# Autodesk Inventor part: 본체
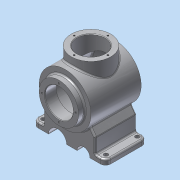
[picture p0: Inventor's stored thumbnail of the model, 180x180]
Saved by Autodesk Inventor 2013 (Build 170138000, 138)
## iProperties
Created: 2018-08
Part Number: 본체
Material: 알루미늄 6061
Document SubType Name: Modeling
Designer: Administrator
Density: 2.71 g/cm^3
Mass: 1888.21 g
Surface Area: 1092.87 cm^2
Volume: 696.756 cm^3
Author: Administrator
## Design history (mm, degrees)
sketch "스케치2"
  geometry: L1 (-70, 40)-(70, 40); L2 (70, 40)-(70, -40); L3 (70, -40)-(-70, -40); L4 (-70, -40)-(-70, 40); L5 (-70, 40)-(70, -40); L6 (70, 40)-(-70, -40); 1 further point
  constraints: 12 end point, 2 midpoint, 2 parallel, 1 horizontal, 1 perpendicular
  dimensions: "d0" = 140 distance of L2.end L3.end; "d1" = 80 distance of L1.end L2.end
extrude "돌출1" new body sketch "스케치2" distance "d2" = 10; taper "d3" = 0 deg
fillet "모깎기1" dims "d4" = 10
sketch "스케치3"
  geometry: L1 (0, 30)-(0, -30) reference; L2 (82, 60)-(82, -60); L3 (120, 60)-(120, 48); L4 (120, 48)-(132, 48); L5 (132, 48)-(132, -48.671); L6 (120, 60)-(82, 60); A1 r 116 centre (82, 56) between (82, -60) and (132, -48.671); 1 further point
  constraints: 10 end point, 2 parallel, 2 perpendicular, 2 point on circle, 1 centre point, 1 horizontal alignment, 1 point on line
  dimensions: "d6" = 120 distance of L2.start L2.end; "d7" = 60 vertical distance of point (0, 0) L2.start; "d8" = 82 distance between parallel lines of L1 L2; "d9" = 76 diameter of L3 L2; "d10" = 100 diameter of L5 L2; "d11" = 12 distance of L3.start L3.end; "d12" = 116 radius of A1
revolve "회전1" sketch "스케치3" stored, may be unused: angle "d13" = 90 deg
sketch "스케치4"
  geometry: L1 (44, 60)-(120, 60) reference; L2 (109, 60)-(109, 38); L3 (109, 38)-(122, 38); L4 (122, 38)-(122, -42.163); L5 (82, 60)-(82, -60); L6 (109, 60)-(82, 60); A1 r 116 centre (82, 56) between (32, -48.671) and (132, -48.671) reference; A2 r 106 centre (82, 56) between (82, -50) and (122, -42.163); 1 further point
  constraints: 10 end point, 3 perpendicular, 3 point on circle, 2 point on line, 1 centre point, 1 midpoint, 1 parallel
  dimensions: "d14" = 54 diameter of L2 L5; "d16" = 22 distance of L2.start L2.end; "d17" = 80 diameter of L4 L5; "d18" = 10 radial gap between concentric circles of A1 A2
revolve "회전2" sketch "스케치4" stored, may be unused: angle "d19" = 90 deg
node "작업 평면1"
chamfer "모따기1" distance "d41" = 1; stored, may be unused: second distance "d42" = 2, angle "d43" = 45 deg
sketch "스케치9"
  geometry: C1 r 38 at (0, 0) reference; 2 further points
  constraints: 1 vertical alignment
  dimensions: "d44" = 32.5 distance of C1.centre point (0, 32.5)
hole "구멍1" sketch "스케치9" at (0, 32.5) diameter "d45" = 3.242; stored, may be unused: countersink angle "d49" = 90 deg, drill point angle "d51" = 118 deg; dims "d46" = 8, "d47" = 4, "d48" = 2, "d50" = 10
fillet "모깎기3" dims "d66" = 3
fillet "모깎기4" dims "d67" = 3
node "작업 평면2"
sketch "스케치13"
  geometry: L1 (60, 0)-(-60, 0) reference; C1 r 32.5 at (0, 82); 1 further point
  constraints: 1 centre point, 1 other
  dimensions: "d73" = 65 diameter of C1; "d74" = 82 distance from line of L1 C1.centre; "d75" = 101.60709 distance of L1.start C1.centre
feature "엠보싱1" sketch "스케치13" dims "d0" = 140, "d1" = 80, "d6" = 120, "d7" = 60, "d8" = 82, "d9" = 76, "d10" = 100, "d11" = 12, "d12" = 116, "d76" = 0.5, "d77" = 0
sketch "스케치15"
  geometry: L1 (0, 10)-(120, 10) reference; L2 (-10, 10)-(-10, 0) reference; L3 (130, 0)-(130, 10) reference; L4 (19.696, 52.41)-(10, 38.563); L5 (110, 38.563)-(100.304, 52.41); L6 (10, 38.563)-(10, 10); L7 (120, 10)-(0, 10) reference; L8 (110, 38.563)-(110, 10); L9 (10, 10)-(110, 10); A1 r 50 centre (60, 82) between (100.304, 52.41) and (19.696, 52.41) reference; A2 r 50 centre (60, 82) between (19.696, 52.41) and (100.304, 52.41); 1 further point
  constraints: 10 end point, 4 point on circle, 2 perpendicular, 2 point on line, 1 centre point, 1 collinear, 1 parallel
  dimensions: "d82" = 35 deg angle of L4 L2; "d83" = 20 distance from line of L6.end L2; "d84" = 20 distance between parallel lines of L3 L8; "d85" = 35 deg angle of L3 L5; "d86" = 0 distance from line of L3.end L5
extrude "돌출4" join sketch "스케치15" distance "d87" = 80; taper "d88" = 0 deg
sketch "스케치16"
  geometry: L1 (120, 0)-(0, 0) reference; C1 r 17.5 at (37.5, 0); 1 further point
  constraints: 1 centre point, 1 point on line
  dimensions: "d89" = 17.5 radius of C1; "d90" = 22.5 distance of C1.centre point (60, 0)
extrude "돌출5" cut sketch "스케치16" stored distance "d91" = 80; taper "d92" = 0 deg
sketch "스케치17"
  geometry: L1 (0, 0)-(-65, 0) reference; C1 r 12.5 at (-32.5, 0); 1 further point
  constraints: 1 centre point, 1 midpoint
  dimensions: "d93" = 12.5 radius of C1; "d94" = 27.5 distance of C1.centre point (-60, 0)
extrude "돌출6" cut sketch "스케치17" stored distance "d95" = 80; taper "d96" = 0 deg
fillet "모깎기5" dims "d97" = 3
fillet "모깎기6" dims "d98" = 3
fillet "모깎기7" dims "d99" = 3
fillet "모깎기8" dims "d100" = 3
fillet "모깎기9" dims "d101" = 3
sketch "스케치18"
  geometry: L1 (-60, 37)-(-53, 37) reference; L2 (-67, -30)-(-67, 30) reference; L3 (-53, -37)-(-60, -37) reference; L4 (-53, 37)-(-53, -37) reference; A1 r 7 centre (-60, 30) between (-60, 37) and (-67, 30) reference; A2 r 7 centre (-60, -30) between (-67, -30) and (-60, -37) reference; 5 further points
  constraints: 2 coincident
hole "구멍3" sketch "스케치18" at (-60, 30), (-60, -30), (60, -28.996), (60, 31.223) diameter "d102" = 8; stored, may be unused: countersink angle "d106" = 90 deg, drill point angle "d108" = 0 deg; dims "d103" = 6, "d104" = 4, "d105" = 2, "d107" = 8
sketch "스케치19"
  geometry: L1 (-50, 48)-(50, 48) reference; C1 r 38 at (0, -2); 1 further point
  constraints: 1 centre point, 1 vertical alignment
  dimensions: "d109" = 76 diameter of C1; "d110" = 50 distance from line of C1.centre L1
extrude "돌출7" join sketch "스케치19" stored distance "d111" = 80; taper "d112" = 0 deg
sketch "스케치20"
  geometry: C1 r 38 at (0, 0) reference; C2 r 27 at (0, 0); 1 further point
  constraints: 1 centre point, 1 coincident
  dimensions: "d113" = 54 diameter of C2
extrude "돌출8" cut sketch "스케치20" distance "d114" = 80; taper "d115" = 0 deg
sketch "스케치21"
  geometry: C1 r 27 at (0, 0) reference; 2 further points
  constraints: 1 vertical alignment
  dimensions: "d116" = 32.5 distance of C1.centre point (0, 32.5)
hole "구멍4" sketch "스케치21" at (0, 32.5) diameter "d117" = 3.242; stored, may be unused: countersink angle "d121" = 90 deg, drill point angle "d123" = 118 deg; dims "d118" = 8, "d119" = 4, "d120" = 2, "d122" = 10
chamfer "모따기2" distance "d127" = 1; stored, may be unused: second distance "d128" = 2, angle "d129" = 45 deg
fillet "모깎기10" dims "d130" = 3
node "솔리드1"
pattern_circular "원형 패턴1" dims angle "d53" = 360 deg
pattern_circular "원형 패턴3" dims angle "d125" = 360 deg
node "투영된 루프2"
other parameters: "d34" = 147
